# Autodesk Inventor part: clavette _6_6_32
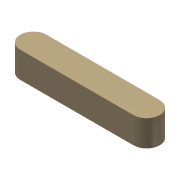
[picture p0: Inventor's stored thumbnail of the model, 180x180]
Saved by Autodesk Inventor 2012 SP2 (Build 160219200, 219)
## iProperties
Created: 2013-04
Part Number: clavette _6_6_32
Material: Default
Document SubType Name: Modeling
Designer: papa
Density: 1 g/cm^3
Mass: 1.10565 g
Surface Area: 7.93646 cm^2
Volume: 1.10565 cm^3
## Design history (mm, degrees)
node "clavette _6_6_321"
node "clavette _6_6_32"
node "Base1"
